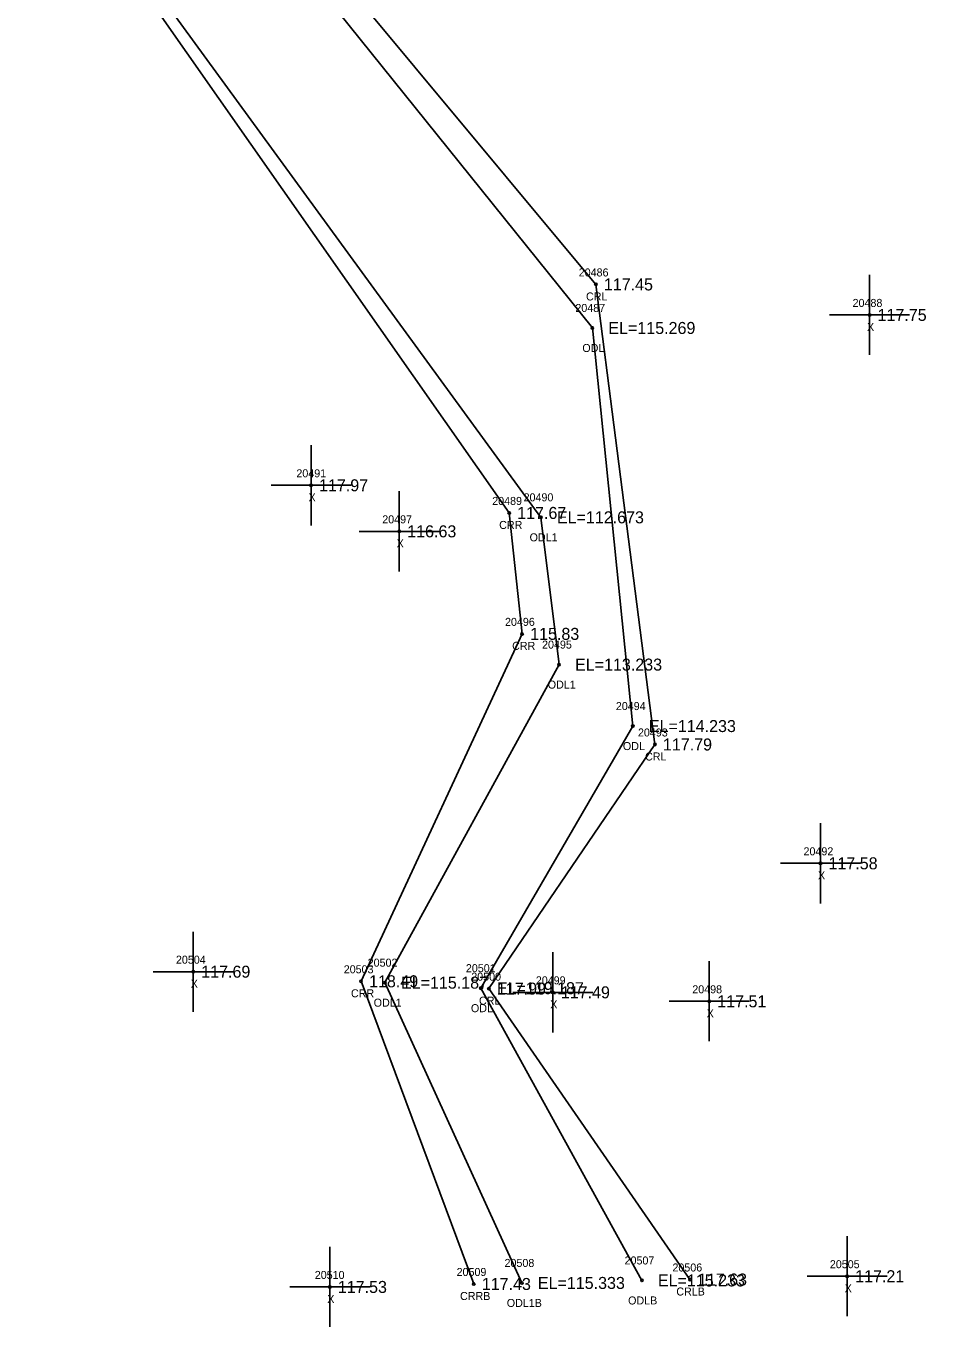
# Model space of a CAD drawing. Extents: x 2375812 to 2377225, y 1024470 to 1025135.
# Drawn here: x 2376503.3 to 2376616.8, y 1024470.5 to 1024633 of the extents above; entities that cross this region are included whole.
import ezdxf

# ---------------------------------------------------------------- set-up
doc = ezdxf.new("R2010")
doc.units = 0
for name, color, linetype in [('RD_EX_H2O', 7, 'Continuous'), ('RD_EX_H2O_txCode', 7, 'Continuous'), ('RD_EX_Misc', 7, 'Continuous'), ('RD_EX_Misc_txCode', 7, 'Continuous'), ('RD_EX_TX_H2O_ELEV', 7, 'Continuous'), ('RD_EX_TX_Misc_ELEV', 7, 'Continuous'), ('RD_SMD_Locator', 7, 'Continuous')]:
    doc.layers.add(name, color=color, linetype=linetype)

msp = doc.modelspace()

# ---------------------------------------------------------------- linework, layer by layer
at = {"layer": 'RD_EX_H2O'}
for points in [[(2376521.35, 1025122.45), (2376536.92, 1025091.14), (2376540.63, 1025083.08), (2376543.66, 1025055.12), (2376543.73, 1025030.97), (2376527.94, 1024982.48), (2376525.52, 1024962.71), (2376529, 1024940.86), (2376531.15, 1024912.48), (2376521.82, 1024868), (2376529.09, 1024848.8), (2376562.19, 1024842.5), (2376569.47, 1024830.15), (2376574.05, 1024803.85), (2376558.51, 1024784.52), (2376559.64, 1024766), (2376613.77, 1024719.65), (2376596.93, 1024694.68), (2376526.36, 1024664.12), (2376525.63, 1024655.55), (2376574.03, 1024595.3), (2376579.09, 1024545.56), (2376560.1, 1024512.81), (2376580.22, 1024476.29)], [(2376510.41, 1025118.87), (2376524.18, 1025090.35), (2376517.39, 1025079.83), (2376512.07, 1025056.47), (2376513.2, 1025032.16), (2376507.89, 1024984.65), (2376510.96, 1024957.77), (2376506.15, 1024940.79), (2376503.27, 1024912.21), (2376508.8, 1024872.61), (2376520.24, 1024833.34), (2376559.55, 1024828.46), (2376560.55, 1024802.93), (2376553.87, 1024788.72), (2376548.34, 1024764.64), (2376601.21, 1024719.97), (2376590.62, 1024704.71), (2376516.74, 1024677.65), (2376510.14, 1024650.4), (2376567.6, 1024571.64), (2376569.87, 1024553.24), (2376548.12, 1024513.5), (2376565.22, 1024475.98)], [(2376554.79, 1024808.22), (2376551.26, 1024790.28), (2376546.73, 1024764.09), (2376597.49, 1024719.36), (2376590.06, 1024708.33), (2376513.66, 1024680), (2376507.07, 1024652.96), (2376563.64, 1024572.19), (2376565.26, 1024557.08), (2376545.13, 1024513.67), (2376559.22, 1024475.85)], [(2376577.78, 1024803.44), (2376559.73, 1024782.76), (2376563.72, 1024768.77), (2376616.84, 1024720.6), (2376596.7, 1024692.16), (2376528.68, 1024662.69), (2376529.24, 1024655.08), (2376574.47, 1024600.74), (2376581.85, 1024543.26), (2376561.1, 1024512.75), (2376586.22, 1024476.41)]]:
    msp.add_lwpolyline(points, dxfattribs=at)
at = {"layer": 'RD_EX_Misc'}
for p, q in [((2376608.67, 1024591.93), (2376608.67, 1024601.93)), ((2376603.67, 1024596.93), (2376613.67, 1024596.93)), ((2376538.88, 1024570.64), (2376538.88, 1024580.64)), ((2376533.88, 1024575.64), (2376543.88, 1024575.64)), ((2376549.9, 1024564.89), (2376549.9, 1024574.89)), ((2376544.9, 1024569.89), (2376554.9, 1024569.89)), ((2376602.54, 1024523.41), (2376602.54, 1024533.41)), ((2376597.54, 1024528.41), (2376607.54, 1024528.41)), ((2376524.16, 1024509.87), (2376524.16, 1024519.87)), ((2376569.09, 1024507.29), (2376569.09, 1024517.29)), ((2376588.64, 1024506.17), (2376588.64, 1024516.17)), ((2376519.16, 1024514.87), (2376529.16, 1024514.87)), ((2376564.09, 1024512.29), (2376574.09, 1024512.29)), ((2376583.64, 1024511.17), (2376593.64, 1024511.17)), ((2376605.87, 1024471.82), (2376605.87, 1024481.82)), ((2376541.23, 1024470.48), (2376541.23, 1024480.48)), ((2376600.87, 1024476.82), (2376610.87, 1024476.82)), ((2376536.23, 1024475.48), (2376546.23, 1024475.48))]:
    msp.add_line(p, q, dxfattribs=at)
at = {"layer": 'RD_SMD_Locator'}
for centre in [(2376574.47, 1024600.74), (2376608.67, 1024596.93), (2376574.03, 1024595.3), (2376538.88, 1024575.64), (2376563.64, 1024572.19), (2376567.6, 1024571.64), (2376549.9, 1024569.89), (2376565.26, 1024557.08), (2376569.87, 1024553.24), (2376579.09, 1024545.56), (2376581.85, 1024543.26), (2376602.54, 1024528.41), (2376524.16, 1024514.87), (2376545.13, 1024513.67), (2376548.12, 1024513.5), (2376560.1, 1024512.81), (2376561.1, 1024512.75), (2376569.09, 1024512.29), (2376588.64, 1024511.17), (2376586.22, 1024476.41), (2376605.87, 1024476.82), (2376541.23, 1024475.48), (2376559.22, 1024475.85), (2376565.22, 1024475.98), (2376580.22, 1024476.29)]:
    msp.add_circle(centre, 0.15, dxfattribs=at)

# ---------------------------------------------------------------- texts
at = {"layer": 'RD_EX_H2O_txCode'}
for s, p in [('20486', (2376572.33, 1024601.74)), ('CRL', (2376573.24, 1024598.74)), ('20487', (2376571.91, 1024597.3)), ('ODL', (2376572.78, 1024592.3)), ('20489', (2376561.52, 1024573.19)), ('20490', (2376565.44, 1024573.64)), ('CRR', (2376562.39, 1024570.19)), ('ODL1', (2376566.19, 1024568.64)), ('20496', (2376563.12, 1024558.08)), ('20495', (2376567.75, 1024555.24)), ('CRR', (2376564.01, 1024555.08)), ('ODL1', (2376568.46, 1024550.24)), ('20494', (2376576.97, 1024547.56)), ('20493', (2376579.73, 1024544.26)), ('ODL', (2376577.85, 1024542.56)), ('CRL', (2376580.62, 1024541.26)), ('20503', (2376542.97, 1024514.67)), ('20502', (2376545.96, 1024515.5)), ('20501', (2376558.23, 1024514.81)), ('20500', (2376558.9, 1024513.75)), ('CRR', (2376543.87, 1024511.67)), ('ODL1', (2376546.71, 1024510.5)), ('ODL', (2376558.86, 1024509.81)), ('CRL', (2376559.87, 1024510.75)), ('20508', (2376563.06, 1024477.98)), ('20507', (2376578.06, 1024478.29)), ('20506', (2376584.04, 1024477.41)), ('20509', (2376557.07, 1024476.85)), ('CRRB', (2376557.5, 1024473.85)), ('CRLB', (2376584.52, 1024474.41)), ('ODL1B', (2376563.34, 1024472.98)), ('ODLB', (2376578.5, 1024473.29))]:
    msp.add_text(s, height=1, dxfattribs=at).set_placement(p)
at = {"layer": 'RD_EX_Misc_txCode'}
for s, p in [('20488', (2376606.55, 1024597.93)), ('X', (2376608.35, 1024594.93)), ('20491', (2376537.05, 1024576.64)), ('X', (2376538.57, 1024573.64)), ('20497', (2376547.78, 1024570.89)), ('X', (2376549.58, 1024567.89)), ('20492', (2376600.42, 1024529.41)), ('X', (2376602.23, 1024526.41)), ('20504', (2376522, 1024515.87)), ('X', (2376523.85, 1024512.87)), ('20499', (2376566.97, 1024513.29)), ('20498', (2376586.52, 1024512.17)), ('X', (2376568.77, 1024510.29)), ('X', (2376588.32, 1024509.17)), ('20505', (2376603.71, 1024477.82)), ('20510', (2376539.35, 1024476.48)), ('X', (2376605.56, 1024474.82)), ('X', (2376540.91, 1024473.48))]:
    msp.add_text(s, height=1, dxfattribs=at).set_placement(p)
at = {"layer": 'RD_EX_TX_H2O_ELEV'}
for s, p in [('117.45', (2376575.47, 1024599.99)), ('EL=115.269', (2376576.03, 1024594.55)), ('117.67', (2376564.64, 1024571.44)), ('EL=112.673', (2376569.6, 1024570.89)), ('115.83', (2376566.26, 1024556.33)), ('EL=113.233', (2376571.87, 1024552.49)), ('EL=114.233', (2376581.09, 1024544.81)), ('117.79', (2376582.85, 1024542.51)), ('118.49', (2376546.13, 1024512.92)), ('EL=115.187', (2376550.12, 1024512.75)), ('117.99', (2376562.1, 1024512)), ('EL=119.187', (2376562.1, 1024512.06)), ('117.43', (2376560.22, 1024475.1)), ('EL=115.333', (2376567.22, 1024475.23)), ('EL=115.233', (2376582.22, 1024475.54)), ('117.63', (2376587.22, 1024475.66))]:
    msp.add_text(s, height=1.5, dxfattribs=at).set_placement(p)
at = {"layer": 'RD_EX_TX_Misc_ELEV'}
for s, p in [('117.75', (2376609.67, 1024596.18)), ('117.97', (2376539.88, 1024574.89)), ('116.63', (2376550.9, 1024569.14)), ('117.58', (2376603.54, 1024527.66)), ('117.69', (2376525.16, 1024514.12)), ('117.49', (2376570.09, 1024511.54)), ('117.51', (2376589.64, 1024510.42)), ('117.21', (2376606.87, 1024476.07)), ('117.53', (2376542.23, 1024474.73))]:
    msp.add_text(s, height=1.5, dxfattribs=at).set_placement(p)

doc.saveas('drawing.dxf')
